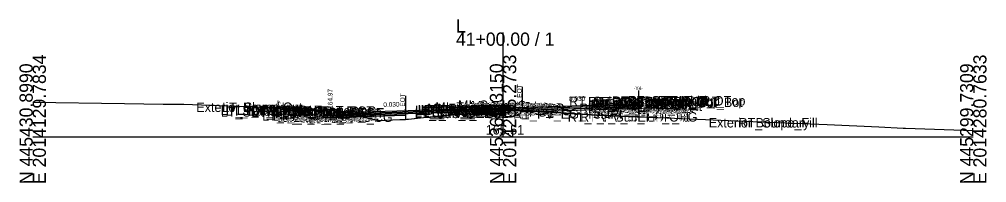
# Model space of a CAD drawing. Extents: x -26 to 4203, y -10 to 9526.
# Drawn here: x 2997.2 to 3202.8, y 990.3 to 1025 of the extents above; entities that cross this region are included whole.
import ezdxf

# ---------------------------------------------------------------- set-up
doc = ezdxf.new("R2010")
doc.units = 0
for name, color, linetype in [('Default', 7, 'Continuous'), ('Exist CMT Pavement', 7, 'Continuous'), ('Exist Cross Section Cell', 7, 'Continuous'), ('Exist XS Center Line Elevation Label', 7, 'Continuous'), ('Exist XS Ground Line', 7, 'Continuous'), ('Prop CMT Conc Surface', 7, 'Continuous'), ('Prop CMT Concrete Structures', 7, 'Continuous'), ('Prop CMT Pvmt Course 1', 7, 'Continuous'), ('Prop CMT Pvmt Course 1 CG', 7, 'Continuous'), ('Prop CMT Pvmt Course 1 Wedge', 7, 'Continuous'), ('Prop CMT Pvmt Course 2', 7, 'Continuous'), ('Prop CMT Pvmt Course 2 Wedge', 7, 'Continuous'), ('Prop CMT Pvmt Course 3', 7, 'Continuous'), ('Prop CMT Pvmt Course 3 Wedge', 7, 'Continuous'), ('Prop CMT Pvmt Surface', 7, 'Continuous'), ('Prop CMT Pvmt Wedge Surface 1', 7, 'Continuous'), ('Prop CMT Pvmt Wedge Surface 2', 7, 'Continuous'), ('Prop CMT Pvmt Wedge Surface 3', 7, 'Continuous'), ('Prop CMT Shear Line', 7, 'Continuous'), ('Prop CMT Shear Line Text', 7, 'Continuous'), ('Prop CMT Slope Grass', 7, 'Continuous'), ('Prop CMT Subgrade Earthwork', 7, 'Continuous'), ('Prop XS Hydro Elevations', 7, 'Continuous'), ('Prop XS Label Text', 7, 'Continuous'), ('Prop XS SE Text', 7, 'Continuous'), ('Prop XS Side Slope Text', 7, 'Continuous'), ('Scratch_Level_0', 7, 'Continuous')]:
    doc.layers.add(name, color=color, linetype=linetype)

msp = doc.modelspace()

# ---------------------------------------------------------------- linework, layer by layer
at = {"layer": 'Exist CMT Pavement'}
for p, q in [((3079.25, 1003.72), (3080.52, 1003.87)), ((3080.52, 1003.87), (3083.72, 1004.2)), ((3083.72, 1004.2), (3085.15, 1004.36)), ((3085.15, 1004.36), (3087.23, 1004.55)), ((3087.23, 1004.55), (3091.44, 1004.93)), ((3091.44, 1004.93), (3092.75, 1005.03)), ((3092.75, 1005.03), (3095.59, 1005.24)), ((3095.59, 1005.24), (3098.99, 1005.46)), ((3098.99, 1005.46), (3100.35, 1005.53)), ((3100.35, 1005.53), (3102.31, 1005.6)), ((3102.31, 1005.6), (3103.18, 1005.62)), ((3103.18, 1005.62), (3104.08, 1005.62))]:
    msp.add_line(p, q, dxfattribs=at)
at = {"layer": 'Exist Cross Section Cell'}
for p, q in [((3100, 1000), (3100, 1022.16)), ((3000, 1000), (3100, 1000)), ((3100, 1000), (3200, 1000))]:
    msp.add_line(p, q, dxfattribs=at)
at = {"layer": 'Exist XS Ground Line'}
msp.add_lwpolyline([(3000, 1007.39), (3019.5, 1007.09), (3027.74, 1006.96), (3032.11, 1006.93), (3043.3, 1006.56), (3049.93, 1006.33), (3050.39, 1006.32), (3051.86, 1006.26), (3066.51, 1005.39), (3069.04, 1004.63), (3073.39, 1003.52), (3078.07, 1003.68), (3079.25, 1003.72), (3079.56, 1003.76), (3079.9, 1003.79), (3080.52, 1003.87), (3081.14, 1003.93), (3082.44, 1004.06), (3083.72, 1004.2), (3085.15, 1004.36), (3085.85, 1004.42), (3087.23, 1004.55), (3089.18, 1004.73), (3091.44, 1004.93), (3092.39, 1005.01), (3092.75, 1005.03), (3095.59, 1005.24), (3096.53, 1005.31), (3098.99, 1005.46), (3099.61, 1005.49), (3100, 1005.51), (3100.35, 1005.53), (3102.31, 1005.6), (3103.18, 1005.62), (3104.17, 1005.62), (3104.96, 1005.61), (3105.86, 1005.49), (3106.48, 1005.46), (3110.11, 1005.29), (3113.42, 1005.03), (3119.87, 1004.61), (3126.68, 1004.37), (3128.43, 1004.29), (3129.14, 1004.24), (3134.85, 1004.09), (3149.59, 1003.44), (3160.14, 1002.99), (3168.91, 1002.61), (3179.92, 1002.14), (3185.06, 1001.89), (3185.56, 1001.87), (3200, 1001.39)], dxfattribs=at)
at = {"layer": 'Prop CMT Conc Surface'}
for points in [[(3058.75, 1005.56), (3053.75, 1005.66)], [(3063.25, 1004.97), (3063.25, 1005.47), (3062.75, 1005.47)], [(3065.25, 1005.11), (3063.25, 1004.97)]]:
    msp.add_lwpolyline(points, dxfattribs=at)
at = {"layer": 'Prop CMT Concrete Structures'}
for points in [[(3102.75, 1006.23), (3102.74, 1006.4), (3101.99, 1006.65), (3097.37, 1006.74), (3092.76, 1006.33), (3092.01, 1006.08), (3092, 1005.91)], [(3092, 1005.91), (3102.75, 1006.23)], [(3053.75, 1005.33), (3053.75, 1005.66)], [(3053.75, 1005.66), (3058.75, 1005.56)], [(3058.75, 1005.23), (3053.75, 1005.33)], [(3058.75, 1005.56), (3058.75, 1005.23)], [(3065.25, 1005.11), (3063.25, 1004.97), (3063.25, 1005.47), (3062.75, 1005.47)], [(3062.75, 1005.47), (3062.75, 1004.45), (3065.25, 1004.53)], [(3065.25, 1004.53), (3065.25, 1005.11)]]:
    msp.add_lwpolyline(points, dxfattribs=at)
at = {"layer": 'Prop CMT Pvmt Course 1'}
for points in [[(3092, 1005.91), (3065.25, 1005.11)], [(3092, 1005.91), (3102.75, 1006.23)], [(3102.75, 1005.98), (3092, 1005.66)], [(3092, 1005.66), (3092, 1005.91)], [(3092, 1005.66), (3092, 1005.91)], [(3102.75, 1006.23), (3128.89, 1007.02)], [(3128.89, 1007.02), (3128.89, 1006.77), (3128.89, 1006.77), (3128.89, 1006.89)], [(3065.25, 1004.86), (3092, 1005.66)], [(3065.25, 1005.11), (3065.25, 1004.86)]]:
    msp.add_lwpolyline(points, dxfattribs=at)
msp.add_lwpolyline([(3092, 1005.66), (3092, 1005.79), (3092, 1005.79), (3092, 1005.66)], close=True, dxfattribs=at)
at = {"layer": 'Prop CMT Pvmt Course 1 CG'}
for points in [[(3128.89, 1006.1), (3128.89, 1006.43)], [(3065.25, 1004.53), (3062.25, 1004.44), (3061.91, 1004.09)], [(3061.91, 1004.09), (3065.25, 1004.19)], [(3065.25, 1004.19), (3065.25, 1004.53)]]:
    msp.add_lwpolyline(points, dxfattribs=at)
at = {"layer": 'Prop CMT Pvmt Course 1 Wedge'}
msp.add_lwpolyline([(3128.89, 1006.89), (3128.89, 1006.77)], dxfattribs=at)
at = {"layer": 'Prop CMT Pvmt Course 2'}
for points in [[(3092, 1005.66), (3128.89, 1006.77)], [(3128.89, 1006.43), (3128.89, 1006.43), (3128.89, 1006.77), (3128.89, 1006.77)], [(3128.89, 1006.77), (3128.89, 1006.43)], [(3092, 1005.66), (3065.25, 1004.86)], [(3065.25, 1004.53), (3092, 1005.33)], [(3065.25, 1004.86), (3065.25, 1004.53)], [(3092, 1005.33), (3092, 1005.66)], [(3092, 1005.33), (3092, 1005.66)], [(3102.75, 1005.65), (3092, 1005.33)]]:
    msp.add_lwpolyline(points, dxfattribs=at)
at = {"layer": 'Prop CMT Pvmt Course 2 Wedge'}
msp.add_lwpolyline([(3128.89, 1006.77), (3128.89, 1006.43)], dxfattribs=at)
at = {"layer": 'Prop CMT Pvmt Course 3'}
for points in [[(3092, 1005.33), (3128.89, 1006.44)], [(3128.89, 1006.43), (3128.89, 1006.43), (3128.89, 1006.1), (3128.89, 1006.1)], [(3128.89, 1006.1), (3128.89, 1006.43)], [(3092, 1005.33), (3065.25, 1004.53)], [(3065.25, 1004.19), (3079.25, 1004.61)], [(3065.25, 1004.53), (3065.25, 1004.19)], [(3092, 1004.99), (3092, 1005.33)], [(3092, 1004.99), (3092, 1005.33)]]:
    msp.add_lwpolyline(points, dxfattribs=at)
at = {"layer": 'Prop CMT Pvmt Course 3 Wedge'}
for points in [[(3128.89, 1006.43), (3128.89, 1004.26)], [(3128.89, 1004.26), (3128.43, 1004.29), (3126.68, 1004.37), (3119.87, 1004.61), (3113.42, 1005.03), (3110.11, 1005.29), (3106.48, 1005.46), (3105.86, 1005.49), (3105.62, 1005.53), (3104.96, 1005.61), (3104.17, 1005.62), (3103.18, 1005.62), (3102.75, 1005.61)]]:
    msp.add_lwpolyline(points, dxfattribs=at)
at = {"layer": 'Prop CMT Pvmt Surface'}
for points in [[(3092, 1005.91), (3065.25, 1005.11)], [(3092, 1005.91), (3102.75, 1006.23)], [(3102.75, 1006.23), (3128.89, 1007.02)]]:
    msp.add_lwpolyline(points, dxfattribs=at)
at = {"layer": 'Prop CMT Pvmt Wedge Surface 1'}
for points in [[(3128.89, 1006.77), (3128.89, 1007.02)], [(3128.89, 1006.89), (3128.89, 1006.77), (3128.89, 1006.77)]]:
    msp.add_lwpolyline(points, dxfattribs=at)
at = {"layer": 'Prop CMT Pvmt Wedge Surface 2'}
msp.add_lwpolyline([(3128.89, 1006.77), (3128.89, 1007.02)], dxfattribs=at)
at = {"layer": 'Prop CMT Pvmt Wedge Surface 3'}
msp.add_lwpolyline([(3128.89, 1006.43), (3128.89, 1007.02)], dxfattribs=at)
at = {"layer": 'Prop CMT Shear Line'}
msp.add_line((3128.89, 1004.85), (3128.89, 1009.86), dxfattribs=at)
at = {"layer": 'Prop CMT Slope Grass'}
msp.add_lwpolyline([(3062.75, 1005.47), (3053.25, 1005.66), (3051.39, 1006.28)], dxfattribs=at)
at = {"layer": 'Prop CMT Subgrade Earthwork'}
for p, q in [((3128.89, 1007.02), (3128.89, 1006.1)), ((3079.25, 1004.61), (3079.25, 1003.72)), ((3092, 1004.99), (3092, 1004.98)), ((3104.08, 1005.62), (3104.08, 1005.36))]:
    msp.add_line(p, q, dxfattribs=at)
for points in [[(3104.08, 1005.36), (3128.89, 1006.1)], [(3128.89, 1006.1), (3128.87, 1004.26)], [(3128.89, 1006.1), (3128.89, 1006.1)], [(3065.25, 1004.19), (3061.91, 1004.09), (3060.48, 1005.51)], [(3079.25, 1004.61), (3065.25, 1004.19)]]:
    msp.add_lwpolyline(points, dxfattribs=at)
at = {"layer": 'Prop XS Label Text'}
for p, q in [((3104.08, 1010.62), (3104.08, 1005.62)), ((3079.25, 1008.72), (3079.25, 1003.72))]:
    msp.add_line(p, q, dxfattribs=at)

# ---------------------------------------------------------------- texts
at = {"layer": 'Default'}
msp.add_text('-', height=0.0001, dxfattribs=at).set_placement((3000, 1000))
at = {"layer": 'Exist Cross Section Cell'}
for s, p in [('L', (3090, 1022.16)), ('41+00.00 / 1', (3090, 1019.36))]:
    msp.add_text(s, height=2.8, dxfattribs=at).set_placement(p)
for s, p in [('E 2014129.7834', (3002.8, 990)), ('E 2014205.2733', (3102.8, 990)), ('E 2014280.7633', (3202.8, 990)), ('N 445430.8990', (3000, 990)), ('N 445365.3150', (3100, 990)), ('N 445299.7309', (3200, 990))]:
    msp.add_text(s, height=2.8, rotation=90, dxfattribs=at).set_placement(p)
at = {"layer": 'Exist XS Center Line Elevation Label'}
msp.add_text('165.51', height=2, dxfattribs=at).set_placement((3096.32, 1000.51))
at = {"layer": 'Prop CMT Shear Line Text'}
msp.add_text('-Y4-', height=0.75, dxfattribs=at).set_placement((3127.8, 1009.97))
at = {"layer": 'Prop XS Hydro Elevations'}
msp.add_text('164.97', height=1, rotation=90, dxfattribs=at).set_placement((3063.75, 1005.97))
at = {"layer": 'Prop XS Label Text'}
for p in [(3103.98, 1006.64), (3079.15, 1004.74)]:
    msp.add_text('E. EOT', height=1, rotation=90, dxfattribs=at).set_placement(p)
at = {"layer": 'Prop XS SE Text'}
for rotation, p in [(1.718, (3114.04, 1007.57)), (1.7173, (3074.56, 1006.35))]:
    msp.add_text('0.030', height=1, rotation=rotation, dxfattribs=at).set_placement(p)
at = {"layer": 'Prop XS Side Slope Text'}
msp.add_text('3:1', height=1, rotation=341.5651, dxfattribs=at).set_placement((3051.59, 1006.84))
at = {"layer": 'Scratch_Level_0'}
for s, p in [('RT_Sub_Trench_Out_DLT', (3114.07, 1006.54)), ('RT_CG_Top_Face', (3118.1, 1006.5)), ('RT_PV1_OEEOP', (3118.71, 1005.89)), ('RT_CG_Top_Gut', (3119.08, 1006)), ('RT_PV1_OEOT', (3119.58, 1006.02)), ('RT_CG_Top_BOC', (3119.63, 1006.5)), ('RT_SDWK_In_Top', (3123.2, 1006.59)), ('RT_SDWK_In_Bot', (3123.23, 1006.25)), ('RT_SDWK_Out_Top', (3126.58, 1006.69)), ('RT_SDWK_Out_Bot', (3126.61, 1006.35)), ('RT_Shld_O', (3132.93, 1006.68)), ('CSLP_Pnt', (3133.76, 1006.69)), ('Exterior Boundary', (3034.78, 1005.31)), ('LT_SDWK_Out_Top', (3039.98, 1004.66)), ('LT_SDWK_Out_Bot', (3040.02, 1004.33)), ('LT_Slope_Cut', (3040.28, 1005.31)), ('LT_Sub_Trench_Out_DLT', (3041.05, 1004.51)), ('LT_CSLP_Pnt', (3043.42, 1004.66)), ('LT_SDWK_In_Top', (3046.61, 1004.56)), ('LT_SDWK_In_Bot', (3046.64, 1004.23)), ('LT_CG_Top_Face', (3050.51, 1004.47)), ('LT_CG_Top_BOC', (3051.03, 1004.47)), ('LT_CG_Top_Gut', (3051.49, 1003.97)), ('LT_PV2_OEOT', (3055.42, 1003.86)), ('LT_PV1_OEOT', (3055.99, 1004.11)), ('LT_Sub_OEEOP', (3081.21, 1003.99)), ('LT_PV2_OEEOP', (3081.31, 1004.66)), ('LT_PV3_OEEOP', (3081.31, 1004.33)), ('LT_PV1_OEEOP', (3081.87, 1004.79)), ('LT_PV2_IEEOP', (3081.95, 1004.66)), ('LT_PV1_IEEOP', (3082.52, 1004.79)), ('LT_PV2_PGL1', (3082.88, 1004.66)), ('LT_PV3_PGL1', (3082.88, 1004.33)), ('LT_PV2_PGL', (3083.21, 1004.66)), ('LT_PV4_PGL', (3083.21, 1003.99)), ('LT_PV1_PGL', (3083.78, 1004.91)), ('MI_Face In', (3083.9, 1005.08)), ('MI_Top In', (3085.61, 1005.33)), ('MI_Crown', (3090.44, 1005.74)), ('RT_PV_IEEOP_EG', (3090.89, 1004.61)), ('RT_PV2_IEEOP', (3092.65, 1004.98)), ('RT_PV3_IEEOP', (3092.65, 1004.65)), ('MI_Face Out', (3093.01, 1005.4)), ('MI_Top Out', (3093.22, 1005.65)), ('RT_PV1_IEEOP', (3093.22, 1005.11)), ('RT_PV2_PGL1', (3093.58, 1004.98)), ('RT_PV3_PGL1', (3093.58, 1004.65)), ('RT_PV2_PGL', (3093.91, 1004.98)), ('RT_PV3_PGL', (3093.91, 1004.65)), ('RT_PV4_PGL', (3093.91, 1004.32)), ('MI_Bot Out', (3094.01, 1005.23)), ('RT_PV1_PGL', (3094.48, 1005.23)), ('RT_PV_EG_TestPt', (3102.18, 1003.87)), ('RT_Sub_OEOT_CG', (3116.21, 1005.1)), ('RT_Sub_OEEOP', (3118.05, 1005.1)), ('RT_PV2_OEEOP', (3118.15, 1005.77)), ('RT_PV3_OEEOP', (3118.15, 1005.43)), ('RT_CG1_Shelf_Out', (3118.39, 1005.53)), ('RT_CG_Bot_IE', (3118.75, 1005.43)), ('RT_Sub_OEOT', (3118.92, 1005.1)), ('RT_PV2_OEOT', (3119.01, 1005.77)), ('RT_PV3_OEOT', (3119.01, 1005.43)), ('RT_CG_Bot_BOC', (3119.66, 1005.51)), ('RT_Sub_OEOP', (3122.28, 1005.2)), ('LT_CG1_Shelf_Out', (3048.8, 1003.44)), ('LT_CG_Bot_BOC', (3051.06, 1003.45)), ('LT_Sub_OEOP', (3052.02, 1003.09)), ('LT_Sub_OEOT_CG', (3052.62, 1003.19)), ('LT_CG_Bot_IE', (3055.16, 1003.53)), ('LT_Sub_OEOT', (3055.33, 1003.19)), ('LT_PV3_OEOT', (3055.42, 1003.53)), ('RT_PV_Sub_Tie_Out', (3113.77, 1003.26)), ('RT_PV_OEEOP_EG', (3116.38, 1003.26)), ('Exterior Boundary', (3143.74, 1002.01)), ('RT_Slope_Fill', (3150.07, 1002.01))]:
    msp.add_text(s, height=2, dxfattribs=at).set_placement(p)

doc.saveas('drawing.dxf')
